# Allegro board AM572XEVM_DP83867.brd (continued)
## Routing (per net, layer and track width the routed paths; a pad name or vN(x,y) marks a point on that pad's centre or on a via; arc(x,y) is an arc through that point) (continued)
DDR1_DQSN0: length 24
  TOP w0.102: U11.AG25 58.6,51.2 58.6,52.28 57.69,53.19 56.03,53.19 54.99,54.23 54.99,58.04 53.34,59.69 50.67,59.69 48.27,57.3 43.42,57.3 43.02,57.7 43.02,57.97 U23.G3
DDR1_DQSN1: length 21.1
  TOP w0.102: U23.B7 47.06,54.81 47.16,54.71 47.16,54.53 47.03,54.4 46.62,54.4 46.52,54.5 46.52,54.64 46.58,54.7 46.58,55.06 46.68,55.16 48.22,55.16 48.37,55.02 48.87,55.02 49.22,54.67 49.22,53.78 49.53,53.47 50.02,53.47 50.33,53.78 50.33,54.91 50.43,55.02 50.64,55.02 50.74,54.91 50.74,53.78 51.05,53.47 51.55,53.47 51.86,53.78 51.86,55.03 51.97,55.15 52.36,55.15 52.46,55.04 52.46,52.31 55.53,49.24 56.55,49.24 U11.AE28
DDR1_DQSN2: length 24.8
  TOP w0.102: U11.AD28 56.53,48.46 54.84,48.46 51.71,51.59 46.89,51.59 46.71,51.41 46.71,49.94 46.86,49.78 48.76,49.78 49.12,49.42 49.12,46.97 48.22,46.06 43.64,46.06 43.33,46.37 43.33,46.69 43.22,46.81 U24.G3
DDR1_DQSN3: length 19.2
  TOP w0.102: U11.Y27 56.98,45.61 52.25,45.61 51.94,45.3 51.94,44.38 52.25,44.07 53.21,44.07 53.47,43.81 53.47,42.42 52.45,41.4 49.65,41.4 49.12,41.93 49.12,43.32 48.09,44.35 47.47,44.35 47.04,43.91 47.04,43.66 U24.B7
DDR1_DQSN_ECC: length 2
  TOP w0.12: U11.V28 v2(56.19,44.01)
  BOTTOM w0.12: R273.2 55.91,44.01 v2(56.19,44.01)
DDR1_ODT0: length 51.1
  TOP w0.12: v2(40.18,60.01) U23.K1 ; v2(40.18,48.81) U24.K1 ; U11.AE20 v2(62.59,49.61)
  INT_L3 w0.094: v2(62.59,49.61) 62.59,49.81 62.16,50.23 62.16,50.56 61.9,50.83 61.63,50.83 61.36,51.09 61.36,51.36 61.1,51.63 60.83,51.63 60.56,51.89 60.56,52.47 59.56,53.47 58.17,53.47 57.15,54.48 57.15,55.5 56.77,55.88 56.6,55.88 56.36,55.64 56.25,55.64 56.16,55.72 56.16,55.84 56.43,56.1 56.43,56.22 56.35,56.3 56.23,56.3 55.97,56.04 55.85,56.04 55.77,56.12 55.77,56.24 56.03,56.5 56.03,56.62 55.95,56.7 55.83,56.7 55.57,56.44 55.45,56.44 55.37,56.52 55.37,56.64 55.63,56.9 55.63,57.02 55.55,57.1 55.43,57.1 55.17,56.84 55.05,56.84 54.97,56.92 54.97,57.04 55.23,57.3 55.23,57.42 55.15,57.5 55.03,57.5 54.77,57.23 54.65,57.23 54.57,57.32 54.57,57.43 54.83,57.7 54.83,57.82 54.75,57.9 54.63,57.9 54.37,57.63 54.25,57.63 54.17,57.72 54.17,57.83 54.44,58.1 54.44,58.21 54.28,58.37 54.16,58.37 53.83,58.04 53.72,58.04 53.63,58.13 53.63,58.24 53.96,58.57 53.96,58.69 51.44,61.21 40.01,61.21 39.75,60.96 39.75,60.44 v2(40.18,60.01) 40.18,59.77 40.58,59.37 40.58,58.22 41.4,57.4 41.4,50.29 40.18,49.07 v2(40.18,48.81)
  BOTTOM w0.12: R360.1 v2(40.18,48.81)
DDR1_RASN: length 50.8
  TOP w0.12: v2(40.98,47.21) U24.J3 ; U11.AF20 v2(63.39,49.61) ; v2(40.98,58.41) U23.J3
  INT_L3 w0.094: v2(63.39,49.61) 62.96,49.18 62.4,49.18 62.16,49.42 62.16,49.76 61.9,50.03 61.63,50.03 61.36,50.29 61.36,50.56 61.1,50.83 60.83,50.83 60.56,51.09 60.56,51.36 60.3,51.63 60.03,51.63 59.76,51.89 59.76,52.16 58.84,53.09 57.66,53.09 56.52,54.23 55.75,54.23 52.99,56.99 52.99,58.38 53.19,58.58 53.19,58.7 53.11,58.78 52.99,58.78 52.79,58.58 52.67,58.58 52.59,58.66 52.59,58.78 52.79,58.98 52.79,59.1 52.71,59.18 52.59,59.18 52.39,58.98 52.27,58.98 52.19,59.06 52.19,59.18 52.39,59.38 52.39,59.49 52.31,59.58 52.19,59.58 51.99,59.38 51.88,59.38 51.79,59.46 51.79,59.58 51.99,59.78 51.99,59.89 51.91,59.98 51.79,59.98 51.59,59.77 51.48,59.77 51.39,59.86 51.39,59.97 51.6,60.17 51.6,60.29 51.51,60.37 51.4,60.37 51.2,60.17 51.08,60.17 51,60.26 51,60.37 51.2,60.57 51.2,60.69 51.11,60.77 51,60.77 50.8,60.57 50.68,60.57 50.42,60.83 41.02,60.83 40.58,60.39 40.58,59.84 40.82,59.61 41.15,59.61 41.38,59.37 41.38,58.81 v2(40.98,58.41) 41.78,57.61 41.78,50.16 40.82,49.21 40.82,49.21 40.58,48.97 40.58,47.61 v2(40.98,47.21)
  BOTTOM w0.12: R372.1 v2(40.98,47.21)
DDR1_RST: length 50
  TOP w0.12: v2(35.38,59.21) U23.T2 ; U11.AG21 v2(61.79,51.21) ; v2(35.38,48.01) U24.T2
  SIG_L5 w0.094: v2(35.38,59.21) 34.98,58.81 34.98,57.91 35.56,57.33 35.56,55.44 34.98,54.86 34.98,52.45 35.38,52.05 TP20.1 35.38,49.68 34.98,49.28 34.98,48.41 v2(35.38,48.01)
  SIG_L8 w0.094: v2(35.38,59.21) 34.92,58.75 34.92,58.06 35.01,57.98 35.35,57.98 35.43,57.89 35.43,57.78 35.35,57.7 35.01,57.7 34.92,57.61 34.92,57.5 35.01,57.41 35.35,57.41 35.43,57.33 35.43,57.21 35.35,57.13 35.01,57.13 34.92,57.05 34.92,56.64 35.31,56.26 44.32,56.26 44.58,56.01 44.58,51.82 44.81,51.58 60.83,51.58 60.83,51.58 61.45,51.58 61.79,51.24 v2(61.79,51.21)
DDR1_WEN: length 50.8
  TOP w0.12: v2(39.38,47.21) U24.L3 ; U11.AH21 v2(61.79,52.01) ; v2(39.38,58.41) U23.L3
  INT_L3 w0.094: v2(39.38,58.41) 39.38,57.9 40.13,57.15 40.13,55.88 38.98,54.73 38.98,47.61 v2(39.38,47.21)
  SIG_L8 w0.094: v2(39.38,58.41) 40.13,57.66 42.07,57.66 42.15,57.58 42.15,57.36 42.23,57.28 42.35,57.28 42.43,57.36 42.43,57.58 42.51,57.66 42.63,57.66 42.71,57.58 42.71,57.36 42.79,57.28 42.91,57.28 42.99,57.36 42.99,57.58 43.08,57.66 43.19,57.66 43.28,57.58 43.28,57.36 43.36,57.28 43.48,57.28 43.56,57.36 43.56,57.58 43.64,57.66 43.76,57.66 43.84,57.58 43.84,57.36 43.92,57.28 44.04,57.28 44.12,57.36 44.12,57.58 44.2,57.66 44.32,57.66 44.4,57.58 44.4,57.36 44.49,57.28 44.6,57.28 44.69,57.36 44.69,57.58 44.77,57.66 44.89,57.66 44.97,57.58 44.97,57.36 45.05,57.28 45.17,57.28 45.25,57.36 45.25,57.58 45.33,57.66 45.45,57.66 45.53,57.58 45.53,57.36 45.61,57.28 45.73,57.28 45.81,57.36 45.81,57.58 45.9,57.66 46.01,57.66 46.1,57.58 46.1,57.36 46.18,57.28 46.3,57.28 46.38,57.36 46.38,57.58 46.46,57.66 46.58,57.66 46.66,57.58 46.66,57.36 46.74,57.28 46.86,57.28 46.94,57.36 46.94,57.58 47.02,57.66 47.14,57.66 47.22,57.58 47.22,57.36 47.31,57.28 47.42,57.28 47.51,57.36 47.51,57.58 47.59,57.66 48.01,57.66 48.16,57.5 48.16,57.38 48.03,57.25 48.03,57.13 48.11,57.05 48.22,57.05 48.36,57.19 48.48,57.19 48.56,57.1 48.56,56.99 48.42,56.85 48.42,56.73 48.51,56.65 48.62,56.65 48.76,56.79 48.88,56.79 48.96,56.7 48.96,56.59 48.82,56.45 48.82,56.33 48.91,56.25 49.02,56.25 49.16,56.39 49.28,56.39 49.36,56.31 49.36,56.19 49.22,56.05 49.22,55.93 49.3,55.85 49.42,55.85 49.56,55.99 49.67,55.99 49.76,55.91 49.76,55.79 49.62,55.65 49.62,55.54 49.7,55.45 49.82,55.45 49.96,55.59 50.07,55.59 50.16,55.51 50.16,55.39 50.02,55.25 50.02,55.14 50.1,55.05 50.22,55.05 50.36,55.19 50.47,55.19 50.55,55.11 50.55,54.99 50.42,54.86 50.42,54.74 50.5,54.66 50.62,54.66 50.75,54.79 50.87,54.79 50.95,54.71 50.95,54.59 50.82,54.46 50.82,54.34 50.9,54.26 51.02,54.26 51.15,54.39 51.27,54.39 51.35,54.31 51.35,54.2 51.21,54.06 51.21,53.94 51.3,53.86 51.41,53.86 51.55,54 51.67,54 51.75,53.91 51.75,53.8 51.61,53.66 51.61,53.54 51.7,53.46 51.81,53.46 51.95,53.6 52.07,53.6 52.15,53.51 52.15,53.4 52.01,53.26 52.01,53.14 52.2,52.96 60.83,52.96 v2(61.79,52.01)
  BOTTOM w0.12: R374.1 v2(39.38,47.21)
DDR2_A0: length 48.3
  TOP w0.12: v2(37.78,24.8) U25.N3 ; U11.R25 v2(58.59,41.61) ; v2(37.78,36) U26.N3
  INT_L3 w0.094: v2(37.78,24.8) 37.38,25.2 37.38,32.25 38.61,33.48 38.61,34.68 37.78,35.51 v2(37.78,36)
  SIG_L8 w0.094: v2(58.59,41.61) 58.13,41.15 54.23,41.15 53.34,40.26 53.21,40.26 52.83,40.64 52.7,40.64 52.55,40.48 52.55,40.37 52.94,39.98 52.94,39.86 52.86,39.78 52.74,39.78 52.35,40.17 52.23,40.17 52.15,40.09 52.15,39.97 52.54,39.58 52.54,39.46 52.46,39.38 52.34,39.38 51.95,39.77 51.83,39.77 51.75,39.69 51.75,39.57 52.14,39.18 52.14,39.06 52.06,38.98 51.94,38.98 51.55,39.37 51.44,39.37 51.35,39.29 51.35,39.17 51.74,38.78 51.74,38.66 51.66,38.58 51.54,38.58 51.15,38.97 51.04,38.97 50.95,38.89 50.95,38.77 51.35,38.38 51.35,38.26 51.26,38.18 51.15,38.18 50.75,38.57 50.64,38.57 50.56,38.49 50.56,38.37 50.82,38.11 50.82,37.99 50.74,37.91 50.62,37.91 50.36,38.17 50.24,38.17 50.08,38.02 50.08,37.9 50.28,37.7 50.28,37.58 50.2,37.5 50.08,37.5 49.88,37.7 49.77,37.7 49.68,37.62 49.68,37.5 49.88,37.3 49.88,37.18 49.8,37.1 49.69,37.1 49.58,37.2 42.28,37.2 42.16,37.08 42.16,35.56 41.78,35.18 38.1,35.18 37.78,35.5 v2(37.78,36)
  BOTTOM w0.12: R355.1 v2(37.78,24.8)
DDR2_A1: length 48.8
  TOP w0.12: v2(36.98,32) U26.P7 ; v2(36.98,20.8) U25.P7 ; U11.R26 v2(57.79,41.61)
  SIG_L8 w0.094: v2(36.98,32) 38.25,33.27 50.93,33.27 54.74,37.08 55.27,37.08 55.35,37.17 55.35,37.51 55.44,37.59 55.55,37.59 55.64,37.51 55.64,37.17 55.72,37.08 55.83,37.08 55.92,37.17 55.92,37.51 56,37.59 56.12,37.59 56.2,37.51 56.2,37.17 56.28,37.08 56.4,37.08 56.48,37.17 56.48,37.51 56.56,37.59 56.68,37.59 56.76,37.51 56.76,37.17 56.85,37.08 56.96,37.08 57.04,37.17 57.04,37.51 57.13,37.59 57.24,37.59 57.33,37.51 57.33,37.17 57.41,37.08 57.8,37.08 58.16,37.45 58.16,37.72 58.47,38.03 58.74,38.03 58.96,38.25 58.96,40.17 59.81,41.01 59.81,41.79 59.57,42.03 58.21,42.03 v2(57.79,41.61)
  SIG_L10 w0.094: v2(36.98,20.8) 36.58,21.2 36.58,21.54 37.03,21.99 37.03,23.95 36.58,24.4 36.58,26.8 37.03,27.25 37.03,28.02 36.58,28.47 36.58,31.6 v2(36.98,32)
  BOTTOM w0.12: R356.1 v2(36.98,20.8)
DDR2_A2: length 48.8
  TOP w0.12: U11.R28 v2(56.19,41.61) ; v2(36.98,36) U26.P3 ; v2(36.98,24.8) U25.P3
  INT_L3 w0.094: v2(36.98,24.8) 36.58,25.2 36.58,32.21 37.85,33.48 37.85,34.65 36.98,35.51 v2(36.98,36)
  SIG_L8 w0.094: v2(36.98,36) 37.38,36.4 37.95,36.4 38.18,36.17 38.18,35.73 38.35,35.56 41.28,35.56 41.78,36.07 41.78,37.72 42.16,38.1 49.02,38.1 49.6,38.68 49.72,38.68 49.85,38.54 49.97,38.54 50.05,38.62 50.05,38.74 49.91,38.88 49.91,38.99 50,39.08 50.11,39.08 50.25,38.94 50.37,38.94 50.45,39.02 50.45,39.14 50.31,39.27 50.31,39.39 50.4,39.47 50.51,39.47 50.65,39.34 50.77,39.34 50.85,39.42 50.85,39.54 50.71,39.67 50.71,39.79 50.79,39.87 50.91,39.87 51.05,39.74 51.17,39.74 51.25,39.82 51.25,39.94 51.11,40.07 51.11,40.19 51.19,40.27 51.31,40.27 51.45,40.13 51.56,40.13 51.65,40.22 51.65,40.33 51.51,40.47 51.51,40.59 51.59,40.67 51.71,40.67 51.85,40.53 51.96,40.53 52.05,40.62 52.05,40.73 51.91,40.87 51.91,40.99 51.99,41.07 52.11,41.07 52.25,40.93 52.36,40.93 52.44,41.01 52.44,41.13 52.31,41.27 52.31,41.39 52.53,41.61 53.11,41.61 53.19,41.69 53.19,42.34 53.27,42.42 53.39,42.42 53.47,42.34 53.47,41.69 53.55,41.61 53.67,41.61 53.75,41.69 53.75,42.34 53.84,42.42 53.95,42.42 54.03,42.34 54.03,41.69 54.12,41.61 54.23,41.61 54.32,41.69 54.32,42.34 54.4,42.42 54.52,42.42 54.6,42.34 54.6,41.69 54.68,41.61 54.8,41.61 54.88,41.69 54.88,42.34 54.96,42.42 55.08,42.42 55.16,42.34 55.16,41.69 55.25,41.61 55.36,41.61 55.44,41.69 55.44,42.34 55.53,42.42 55.64,42.42 55.73,42.34 55.73,41.69 55.81,41.61 v2(56.19,41.61)
  BOTTOM w0.12: R346.1 v2(36.98,24.8)
DDR2_A3: length 49.9
  TOP w0.12: U11.R27 v2(56.99,41.61) ; v2(37.78,36.8) U26.N2 ; v2(37.78,25.6) U25.N2
  SIG_L5 w0.094: v2(56.99,41.61) 56.53,41.15 55.48,41.15 55.4,41.23 55.4,41.57 55.32,41.66 55.2,41.66 55.12,41.57 55.12,41.23 55.04,41.15 54.92,41.15 54.84,41.23 54.84,41.57 54.76,41.66 54.64,41.66 54.56,41.57 54.56,41.23 54.47,41.15 54.36,41.15 54.27,41.23 54.27,41.57 54.19,41.66 54.07,41.66 53.99,41.57 53.99,40.84 53.9,40.75 53.14,40.75 53.06,40.83 53.06,41.57 52.98,41.66 52.86,41.66 52.78,41.57 52.78,40.83 52.69,40.75 52.58,40.75 52.49,40.83 52.49,41.57 52.41,41.66 52.29,41.66 52.21,41.57 52.21,40.83 52.13,40.75 52.01,40.75 51.93,40.83 51.93,41.57 51.85,41.66 51.73,41.66 51.65,41.57 51.65,40.83 51.57,40.75 51.45,40.75 51.37,40.83 51.37,41.57 51.28,41.66 51.17,41.66 51.08,41.57 51.08,40.83 51,40.75 50.88,40.75 50.8,40.83 50.8,41.57 50.72,41.66 50.6,41.66 50.52,41.57 50.52,40.83 50.34,40.65 50.22,40.65 50,40.87 49.89,40.87 49.8,40.79 49.8,40.67 50.03,40.45 50.03,40.33 49.94,40.25 49.83,40.25 49.6,40.47 49.49,40.47 49.41,40.39 49.41,40.27 49.63,40.05 49.63,39.93 48.94,39.24 39.66,39.24 38.18,37.77 38.18,37.17 37.82,36.8 v2(37.78,36.8) 37.78,36.68 37.38,36.28 37.38,33.1 38.23,32.26 38.23,29.89 38.1,29.76 38.1,29.61 38.23,29.48 38.23,29.32 38.1,29.2 38.1,29.04 38.23,28.92 38.23,28.76 38.1,28.63 38.1,28.48 38.23,28.35 38.23,28.2 38.1,28.07 38.1,27.91 38.23,27.79 38.23,27.63 38.1,27.51 38.1,27.35 38.23,27.22 38.23,27.07 38.1,26.94 38.1,26.79 38.23,26.66 38.23,26.05 v2(37.78,25.6)
  BOTTOM w0.12: v2(37.78,25.6) 38.18,26 38.18,26.6 R344.1
DDR2_A4: length 50
  TOP w0.12: v2(36.98,31.2) U26.P8 ; U11.P23 v2(60.19,40.01) ; v2(36.98,20) U25.P8
  SIG_L8 w0.094: v2(60.19,40.01) 60.61,39.58 60.61,39.05 60.83,38.83 61.12,38.83 61.36,38.59 61.36,38.25 61.14,38.03 61.1,37.98 60.83,37.98 60.61,37.76 60.61,37.5 60.56,37.45 60.56,37.45 60.34,37.23 60.3,37.18 60.03,37.18 59.81,36.96 59.81,36.7 59.76,36.65 59.76,36.65 59.54,36.43 59.5,36.38 59.23,36.38 59.01,36.16 59.01,35.9 58.96,35.85 58.96,35.85 58.74,35.63 58.7,35.58 58.43,35.58 58.21,35.36 58.21,35.1 58.16,35.05 58.16,35.05 57.94,34.83 57.91,34.8 57.53,34.8 55.65,32.91 55.65,31.39 54.74,30.48 50.55,30.48 49.02,28.96 40.13,28.96 38.98,30.11 38.98,31.38 38.75,31.6 U26.P8 v2(36.98,31.2) 36.58,30.8 36.58,29.92 37.08,29.42 37.08,27.37 36.58,26.87 36.58,24.33 37.08,23.83 37.08,21.79 36.58,21.29 36.58,20.4 v2(36.98,20)
  BOTTOM w0.12: R347.1 37.38,19 37.38,19.6 v2(36.98,20)
DDR2_A5: length 49.5
  TOP w0.12: U11.P22 v2(60.99,40.01) ; v2(36.98,36.8) U26.P2 ; v2(36.98,25.6) U25.P2
  SIG_L5 w0.094: v2(60.99,40.01) 60.61,40.38 60.61,41.72 60.3,42.03 55.75,42.03 55.66,42.11 55.66,42.34 55.58,42.42 55.46,42.42 55.38,42.34 55.38,42.11 55.3,42.03 55.18,42.03 55.1,42.11 55.1,42.34 55.02,42.42 54.9,42.42 54.82,42.34 54.82,42.11 54.74,42.03 54.62,42.03 54.54,42.11 54.54,42.34 54.45,42.42 54.34,42.42 54.25,42.34 54.25,42.11 54.17,42.03 54.05,42.03 53.97,42.11 53.97,42.34 53.89,42.42 53.77,42.42 53.69,42.34 53.69,42.11 53.61,42.03 53.49,42.03 53.41,42.11 53.41,42.34 53.33,42.42 53.21,42.42 53.13,42.34 53.13,42.11 53.04,42.03 52.93,42.03 52.84,42.11 52.84,42.34 52.76,42.42 52.64,42.42 52.56,42.34 52.56,42.11 52.48,42.03 52.36,42.03 52.28,42.11 52.28,42.34 52.2,42.42 52.08,42.42 52,42.34 52,42.11 51.92,42.03 51.8,42.03 51.72,42.11 51.72,42.34 51.63,42.42 51.52,42.42 51.43,42.34 51.43,42.11 51.35,42.03 51.24,42.03 51.15,42.11 51.15,42.34 51.07,42.42 50.95,42.42 50.87,42.34 50.87,42.11 50.79,42.03 50.16,42.03 48.26,40.13 39.37,40.13 37.38,38.14 37.38,37.26 36.98,36.86 v2(36.98,36.8) 36.98,36.68 36.58,36.28 36.58,33.01 37.34,32.26 37.34,29.87 37.21,29.75 37.21,29.59 37.34,29.46 37.34,29.31 37.21,29.18 37.21,29.03 37.34,28.9 37.34,28.74 37.21,28.62 37.21,28.46 37.34,28.34 37.34,28.18 37.21,28.05 37.21,27.9 37.34,27.77 37.34,27.62 37.21,27.49 37.21,27.34 37.34,27.21 37.34,27.05 37.21,26.93 37.21,26.77 37.34,26.64 37.34,25.96 v2(36.98,25.6)
  BOTTOM w0.12: v2(36.98,25.6) 37.38,26 37.38,26.6 R345.1
DDR2_A6: length 49.5
  TOP w0.12: v2(36.18,20) U25.R8 ; v2(36.18,31.2) U26.R8 ; U11.P25 v2(58.59,40.01)
  SIG_L8 w0.094: v2(58.59,40.01) 58.21,39.63 58.21,38.27 57.92,37.98 55,37.98 54.83,37.81 54.71,37.81 54.55,37.98 54.43,37.98 54.35,37.89 54.35,37.78 54.51,37.61 54.51,37.5 54.43,37.41 54.32,37.41 54.15,37.58 54.04,37.58 53.95,37.49 53.95,37.38 54.12,37.21 54.12,37.1 54.03,37.02 53.92,37.02 53.75,37.18 53.64,37.18 53.55,37.1 53.55,36.98 53.72,36.82 53.72,36.7 53.63,36.62 53.52,36.62 53.35,36.78 53.24,36.78 53.16,36.7 53.16,36.58 53.32,36.42 53.32,36.3 53.24,36.22 53.12,36.22 52.96,36.38 52.84,36.38 52.76,36.3 52.76,36.18 52.92,36.02 52.92,35.9 52.84,35.82 52.72,35.82 52.56,35.98 52.44,35.98 52.36,35.9 52.36,35.78 52.52,35.62 52.52,35.5 52.44,35.42 52.32,35.42 52.16,35.58 52.04,35.58 51.96,35.5 51.96,35.38 52.12,35.22 52.12,35.1 52.04,35.02 51.92,35.02 51.76,35.19 51.64,35.19 51.56,35.1 51.56,34.99 51.72,34.82 51.72,34.71 51.64,34.62 51.52,34.62 51.36,34.79 51.24,34.79 51.16,34.7 51.16,34.59 51.33,34.42 51.33,34.31 51.24,34.22 51.13,34.22 50.96,34.39 50.85,34.39 50.76,34.3 50.76,34.19 50.93,34.03 50.93,33.91 50.67,33.66 37.08,33.66 36.58,33.15 U26.R8 v2(36.18,31.2) 35.78,30.8 35.78,29.92 36.32,29.38 36.32,27.41 35.78,26.87 35.78,24.33 36.2,23.92 36.2,21.7 35.78,21.29 35.78,20.4 v2(36.18,20)
  BOTTOM w0.12: v2(36.18,20) 36.58,19.6 36.58,19 R338.1
DDR2_A7: length 50.1
  TOP w0.12: v2(36.18,36.8) U26.R2 ; U11.N20 v2(62.59,39.21) ; v2(36.18,25.6) U25.R2
  SIG_L5 w0.094: v2(62.59,39.21) 62.21,39.58 62.21,41.72 61.94,41.98 60.83,41.98 60.58,42.24 60.58,42.55 60.56,42.56 60.56,42.56 60.34,42.78 60.33,42.8 54.8,42.8 54.72,42.88 54.72,42.97 54.63,43.05 54.52,43.05 54.43,42.97 54.43,42.88 54.35,42.8 54.24,42.8 54.15,42.88 54.15,42.97 54.07,43.05 53.95,43.05 53.87,42.97 53.87,42.88 53.79,42.8 53.67,42.8 53.59,42.88 53.59,42.97 53.51,43.05 53.39,43.05 53.31,42.97 53.31,42.88 53.22,42.8 53.11,42.8 53.02,42.88 53.02,42.97 52.94,43.05 52.83,43.05 52.74,42.97 52.74,42.88 52.66,42.8 52.54,42.8 52.46,42.88 52.46,42.97 52.38,43.05 52.26,43.05 52.18,42.97 52.18,42.88 52.1,42.8 51.98,42.8 51.9,42.88 51.9,42.97 51.81,43.05 51.7,43.05 51.62,42.97 51.62,42.88 51.53,42.8 50.42,42.8 48.13,40.51 39.12,40.51 36.58,37.98 36.58,37.22 36.18,36.82 v2(36.18,36.8) 36.18,36.56 36.02,36.4 36.02,36.4 35.78,36.17 35.78,33.05 36.58,32.26 36.58,29.9 36.45,29.78 36.45,29.62 36.58,29.49 36.58,29.34 36.45,29.21 36.45,29.06 36.58,28.93 36.58,28.78 36.45,28.65 36.45,28.49 36.58,28.37 36.58,28.21 36.45,28.09 36.45,27.93 36.58,27.8 36.58,27.65 36.45,27.52 36.45,27.37 36.58,27.24 36.58,27.08 36.45,26.96 36.45,26.8 36.58,26.68 36.58,26 v2(36.18,25.6)
  BOTTOM w0.12: R358.1 36.58,26.6 36.58,26 v2(36.18,25.6)
DDR2_A8: length 49.8
  TOP w0.12: U11.P27 v2(56.99,40.01) ; v2(35.38,20) U25.T8 ; v2(35.38,31.2) U26.T8
  SIG_L8 w0.094: v2(56.99,40.01) 57.4,39.59 57.4,39.09 57.14,38.83 55.88,38.83 55.46,39.24 54.74,39.24 50.67,35.18 50.3,35.18 50.22,35.1 50.22,34.88 50.14,34.8 50.02,34.8 49.94,34.88 49.94,35.1 49.85,35.18 49.74,35.18 49.65,35.1 49.65,34.88 49.57,34.8 49.46,34.8 49.37,34.88 49.37,35.1 49.29,35.18 49.17,35.18 49.09,35.1 49.09,34.88 49.01,34.8 48.89,34.8 48.81,34.88 48.81,35.1 48.73,35.18 48.61,35.18 48.53,35.1 48.53,34.88 48.44,34.8 48.33,34.8 48.24,34.88 48.24,35.1 48.16,35.18 48.05,35.18 47.96,35.1 47.96,34.88 47.88,34.8 47.76,34.8 47.68,34.88 47.68,35.1 47.6,35.18 47.48,35.18 47.4,35.1 47.4,34.88 47.32,34.8 47.2,34.8 47.12,34.88 47.12,35.1 47.03,35.18 46.92,35.18 46.84,35.1 46.84,34.88 46.75,34.8 46.64,34.8 46.55,34.88 46.55,35.1 46.47,35.18 46.35,35.18 46.27,35.1 46.27,34.88 46.19,34.8 46.07,34.8 45.99,34.88 45.99,35.1 45.91,35.18 45.79,35.18 45.71,35.1 45.71,34.88 45.62,34.8 45.51,34.8 45.43,34.88 45.43,35.1 45.34,35.18 45.23,35.18 45.14,35.1 45.14,34.88 45.06,34.8 44.94,34.8 44.86,34.88 44.86,35.1 44.78,35.18 44.66,35.18 44.58,35.1 44.58,34.88 44.5,34.8 44.38,34.8 44.3,34.88 44.3,35.1 44.21,35.18 43.43,35.18 42.61,34.35 36.64,34.35 35.78,33.5 U26.T8 v2(35.38,31.2) 34.98,30.8 34.98,30.05 34.54,29.61 34.54,27.31 34.98,26.87 34.98,24.46 35.43,24.01 35.43,21.74 34.98,21.29 34.98,20.4 v2(35.38,20)
  BOTTOM w0.12: v2(35.38,20) 35.78,19.6 35.78,19 R359.1
DDR2_A9: length 48.4
  TOP w0.12: U11.N27 v2(56.99,39.21) ; v2(36.18,24.8) U25.R3 ; v2(36.18,36) U26.R3
  INT_L3 w0.094: v2(36.18,24.8) 35.78,25.2 35.78,32.18 37.08,33.48 37.08,34.61 36.18,35.51 v2(36.18,36)
  SIG_L8 w0.094: v2(56.99,39.21) 56.61,39.58 53.68,39.58 53.49,39.39 53.49,39.27 53.81,38.95 53.81,38.83 53.73,38.75 53.61,38.75 53.29,39.07 53.17,39.07 53.09,38.99 53.09,38.87 53.42,38.55 53.42,38.43 53.33,38.35 53.22,38.35 52.89,38.67 52.77,38.67 52.69,38.59 52.69,38.48 53.02,38.15 53.02,38.03 52.93,37.95 52.82,37.95 52.49,38.28 52.37,38.28 52.29,38.19 52.29,38.08 52.62,37.75 52.62,37.63 52.54,37.55 52.42,37.55 52.09,37.88 51.97,37.88 51.89,37.79 51.89,37.68 52.22,37.35 52.22,37.23 52.14,37.15 52.02,37.15 51.69,37.48 51.58,37.48 51.49,37.4 51.49,37.28 51.82,36.95 51.82,36.83 51.74,36.75 51.62,36.75 51.42,36.95 51.3,36.95 51.22,36.87 51.22,36.75 51.42,36.55 51.42,36.44 51.34,36.35 51.22,36.35 50.89,36.68 50.78,36.68 50.7,36.6 50.7,36.48 51.02,36.15 51.02,36.04 50.94,35.95 50.82,35.95 50.5,36.28 50.38,36.28 50.3,36.2 50.3,36.08 50.62,35.76 50.62,35.64 50.54,35.56 50.43,35.56 50.1,35.88 49.98,35.88 49.66,35.56 43.31,35.56 42.42,34.67 36.2,34.67 35.81,35.05 35.81,35.64 v2(36.18,36)
  BOTTOM w0.12: R336.1 v2(36.18,24.8)
DDR2_A10: length 48
  TOP w0.12: v2(39.38,20.8) U25.L7 ; v2(39.38,32) U26.L7 ; U11.N23 v2(60.19,39.21)
  SIG_L8 w0.094: v2(60.19,39.21) 60.19,39 60.58,38.61 60.58,38.26 60.34,38.03 60.03,38.03 59.76,37.76 59.76,37.45 59.54,37.23 59.23,37.23 58.16,36.16 58.16,35.85 57.94,35.63 57.47,35.63 56.32,34.48 56.2,34.48 55.94,34.74 55.82,34.74 55.74,34.66 55.74,34.54 56,34.28 56,34.16 55.92,34.08 55.8,34.08 55.54,34.34 55.42,34.34 55.34,34.26 55.34,34.14 55.6,33.88 55.6,33.76 55.52,33.68 55.41,33.68 55.14,33.94 55.02,33.94 54.94,33.86 54.94,33.74 55.21,33.48 55.21,33.36 55.12,33.28 55.01,33.28 54.74,33.54 54.63,33.54 54.54,33.46 54.54,33.34 54.81,33.08 54.81,32.96 54.72,32.88 54.61,32.88 54.34,33.14 54.23,33.14 54.14,33.06 54.14,32.95 54.41,32.68 54.41,32.56 53.98,32.13 53.98,31.24 53.72,30.99 50.29,30.99 48.64,29.34 40.26,29.34 39.78,29.81 39.78,31.6 v2(39.38,32)
  SIG_L10 w0.094: v2(39.38,20.8) 38.98,21.2 38.98,21.54 39.43,21.99 39.43,23.95 38.98,24.4 38.98,26.8 39.43,27.25 39.43,29.67 38.98,30.12 38.98,31.6 v2(39.38,32)
  BOTTOM w0.12: R340.1 v2(39.38,20.8)
DDR2_A11: length 48.3
  TOP w0.12: U11.P26 v2(57.79,40.01) ; v2(36.18,32) U26.R7 ; v2(36.18,20.8) U25.R7
  SIG_L8 w0.094: v2(57.79,40.01) 57.79,38.94 57.33,38.48 55.75,38.48 55.37,38.86 54.86,38.86 50.22,34.22 50.22,34.12 50.14,34.04 50.02,34.04 49.94,34.12 49.94,34.33 49.86,34.42 49.74,34.42 49.66,34.33 49.66,34.12 49.58,34.04 49.46,34.04 49.38,34.12 49.38,34.33 49.29,34.42 49.18,34.42 49.09,34.33 49.09,34.12 49.01,34.04 48.9,34.04 48.81,34.12 48.81,34.33 48.73,34.42 48.61,34.42 48.53,34.33 48.53,34.12 48.45,34.04 48.33,34.04 48.25,34.12 48.25,34.33 48.17,34.42 48.05,34.42 47.97,34.33 47.97,34.12 47.88,34.04 47.77,34.04 47.68,34.12 47.68,34.33 47.6,34.42 47.49,34.42 47.4,34.33 47.4,34.12 47.32,34.04 47.2,34.04 47.12,34.12 47.12,34.33 47.04,34.42 46.92,34.42 46.84,34.33 46.84,34.12 46.76,34.04 46.64,34.04 46.56,34.12 46.56,34.33 46.47,34.42 46.36,34.42 46.28,34.33 46.28,34.12 46.19,34.04 46.08,34.04 45.99,34.12 45.99,34.33 45.91,34.42 45.79,34.42 45.71,34.33 45.71,34.12 45.63,34.04 45.51,34.04 45.43,34.12 45.43,34.33 45.35,34.42 45.23,34.42 45.15,34.33 45.15,34.12 45.06,34.04 44.95,34.04 44.87,34.12 44.87,34.33 44.78,34.42 44.67,34.42 44.58,34.33 44.58,34.12 44.5,34.04 44.38,34.04 44.3,34.12 44.3,34.33 44.22,34.42 44.1,34.42 44.02,34.33 44.02,34.12 43.94,34.04 43.82,34.04 43.74,34.12 43.74,34.62 43.64,34.72 43.48,34.72 42.8,34.04 36.96,34.04 36.2,33.27 36.2,32.02 v2(36.18,32)
  SIG_L10 w0.094: v2(36.18,32) 35.78,31.6 35.78,28.47 36.23,28.02 36.23,27.25 35.78,26.8 35.78,24.4 36.23,23.95 36.23,21.99 35.78,21.54 35.78,21.2 v2(36.18,20.8)
  BOTTOM w0.12: R337.1 v2(36.18,20.8)
DDR2_A12: length 48.5
  TOP w0.12: v2(37.78,32) U26.N7 ; v2(37.78,20.8) U25.N7 ; U11.N28 v2(56.19,39.21)
  SIG_L8 w0.094: v1(55.25,36.01) 51.75,32.51 51.57,32.51 51.49,32.59 51.49,32.81 51.41,32.89 51.29,32.89 51.21,32.81 51.21,32.59 51.13,32.51 51.01,32.51 50.93,32.59 50.93,32.81 50.85,32.89 50.73,32.89 50.65,32.81 50.65,32.59 50.56,32.51 50.45,32.51 50.36,32.59 50.36,32.81 50.28,32.89 50.16,32.89 50.08,32.81 50.08,32.59 50,32.51 49.88,32.51 49.8,32.59 49.8,32.81 49.72,32.89 49.6,32.89 49.52,32.81 49.52,32.59 49.44,32.51 49.32,32.51 49.24,32.59 49.24,32.81 49.15,32.89 49.04,32.89 48.95,32.81 48.95,32.59 48.87,32.51 48.75,32.51 48.67,32.59 48.67,32.81 48.59,32.89 48.47,32.89 48.39,32.81 48.39,32.59 48.31,32.51 48.19,32.51 48.11,32.59 48.11,32.81 48.03,32.89 47.91,32.89 47.83,32.81 47.83,32.59 47.74,32.51 47.63,32.51 47.54,32.59 47.54,32.81 47.46,32.89 47.35,32.89 47.26,32.81 47.26,32.59 47.18,32.51 47.06,32.51 46.98,32.59 46.98,32.81 46.9,32.89 46.78,32.89 46.7,32.81 46.7,32.59 46.62,32.51 46.5,32.51 46.42,32.59 46.42,32.81 46.33,32.89 46.22,32.89 46.13,32.81 46.13,32.59 46.05,32.51 45.94,32.51 45.85,32.59 45.85,32.81 45.77,32.89 45.65,32.89 45.57,32.81 45.57,32.59 45.49,32.51 45.37,32.51 45.29,32.59 45.29,32.81 45.21,32.89 45.09,32.89 45.01,32.81 45.01,32.59 44.92,32.51 44.81,32.51 44.73,32.59 44.73,32.81 44.64,32.89 44.53,32.89 44.44,32.81 44.44,32.59 44.36,32.51 44.24,32.51 44.16,32.59 44.16,32.81 44.08,32.89 43.96,32.89 43.88,32.81 43.88,32.59 43.8,32.51 43.68,32.51 43.6,32.59 43.6,32.81 43.51,32.89 43.4,32.89 43.32,32.81 43.32,32.59 43.23,32.51 43.12,32.51 43.03,32.59 43.03,32.81 42.95,32.89 42.83,32.89 42.75,32.81 42.75,32.59 42.67,32.51 42.55,32.51 42.47,32.59 42.47,32.81 42.39,32.89 42.27,32.89 42.19,32.81 42.19,32.59 42.1,32.51 41.99,32.51 41.91,32.59 41.91,32.81 41.82,32.89 41.71,32.89 41.62,32.81 41.62,32.59 41.54,32.51 41.42,32.51 41.34,32.59 41.34,32.81 41.26,32.89 41.14,32.89 41.06,32.81 41.06,32.59 40.98,32.51 40.86,32.51 40.78,32.59 40.78,32.81 40.7,32.89 38.67,32.89 v2(37.78,32)
  SIG_L10 w0.094: v2(37.78,32) 37.38,31.6 37.38,28.47 37.83,28.02 37.83,27.25 37.38,26.8 37.38,24.4 37.83,23.95 37.83,21.99 37.38,21.54 37.38,21.2 v2(37.78,20.8) ; v2(56.19,39.21) 56.19,36.95 v1(55.25,36.01)
  BOTTOM w0.12: R354.1 v2(37.78,20.8)
DDR2_A13: length 48.7
  TOP w0.12: v2(35.38,36) U26.T3 ; U11.T22 v2(60.99,42.41) ; v2(35.38,24.8) U25.T3
  INT_L3 w0.094: v2(35.38,24.8) 34.98,25.2 34.98,32.17 36.32,33.51 36.32,34.62 35.38,35.56 v2(35.38,36)
  SIG_L5 w0.094: v2(35.38,36) 35.38,36.24 35.78,36.64 35.78,37.94 38.73,40.89 48.01,40.89 50.69,43.58 51.41,43.58 51.49,43.66 51.49,43.86 51.58,43.94 51.69,43.94 51.78,43.86 51.78,43.66 51.86,43.58 51.98,43.58 52.06,43.66 52.06,43.86 52.14,43.94 52.26,43.94 52.34,43.86 52.34,43.66 52.42,43.58 52.54,43.58 52.62,43.66 52.62,43.86 52.71,43.94 52.82,43.94 52.9,43.86 52.9,43.66 52.99,43.58 53.1,43.58 53.19,43.66 53.19,43.86 53.27,43.94 53.39,43.94 53.47,43.86 53.47,43.66 53.55,43.58 53.67,43.58 53.75,43.66 53.75,43.86 53.83,43.94 53.95,43.94 54.03,43.86 54.03,43.66 54.11,43.58 54.23,43.58 54.31,43.66 54.31,43.86 54.4,43.94 54.51,43.94 54.6,43.86 54.6,43.66 54.68,43.58 54.8,43.58 54.88,43.66 54.88,43.86 54.96,43.94 55.08,43.94 55.16,43.86 55.16,43.66 55.24,43.58 60.34,43.58 60.61,43.32 60.61,43.05 60.99,42.67 v2(60.99,42.41)
  BOTTOM w0.12: R357.1 v2(35.38,24.8)
DDR2_A14: length 48.5
  TOP w0.12: v2(35.38,32) U26.T7 ; v2(35.38,20.8) U25.T7 ; U11.R22 v2(60.99,41.61)
  SIG_L10 w0.094: v2(60.99,41.61) 60.56,42.03 60.56,42.56 60.34,42.78 60.03,42.78 59.76,43.05 59.76,43.36 59.54,43.58 59.23,43.58 57.63,45.18 55.98,45.18 55.75,44.96 55.75,44.77 51.75,40.77 45.09,40.77 41.78,37.47 41.78,36.2 40.64,35.05 38.43,35.05 v2(35.38,32) 34.98,31.6 34.98,28.47 35.43,28.02 35.43,27.25 34.98,26.8 34.98,24.4 35.43,23.95 35.43,21.99 34.98,21.54 34.98,21.2 v2(35.38,20.8)
  BOTTOM w0.12: R339.1 v2(35.38,20.8)
DDR2_A15: length 48.2
  TOP w0.12: v2(38.58,20.8) U25.M7 ; U11.U22 v2(60.99,43.21) ; v2(38.58,32) U26.M7
  SIG_L8 w0.094: v2(38.58,32) 39.09,32.51 40.39,32.51 40.58,32.32 40.58,30.03 40.89,29.72 48.26,29.72 50.04,31.5 51.44,31.5 55.12,35.18 56.39,35.18 56.56,35.35 56.56,36.24 56.75,36.43 57.64,36.43 58.44,37.23 58.74,37.23 58.96,37.45 58.96,37.75 59.24,38.03 59.54,38.03 59.81,38.29 59.81,40.25 60.58,41.02 60.58,42.8 v2(60.99,43.21)
  SIG_L10 w0.094: v2(38.58,32) 38.58,31.85 38.18,31.45 38.18,28.47 38.63,28.02 38.63,27.25 38.18,26.8 38.18,24.4 38.63,23.95 38.63,21.99 38.18,21.54 38.18,21.2 v2(38.58,20.8)
  BOTTOM w0.12: R342.1 v2(38.58,20.8)
DDR2_BA0: length 48.5
  TOP w0.12: v2(38.58,36.8) U26.M2 ; v2(38.58,25.6) U25.M2 ; U11.U23 v2(60.19,43.21)
  SIG_L5 w0.094: v2(38.58,25.6) 38.94,25.97 38.94,32.3 38.18,33.06 38.18,36.28 38.58,36.68 v2(38.58,36.8)
  SIG_L8 w0.094: v2(38.58,36.8) 38.18,37.2 38.18,39.07 40.26,41.15 48.39,41.15 48.77,41.53 48.77,42.16 49.26,42.65 49.26,42.77 49.05,42.97 49.05,43.09 49.14,43.17 49.25,43.17 49.45,42.97 49.57,42.97 49.65,43.05 49.65,43.17 49.45,43.37 49.45,43.48 49.54,43.57 49.65,43.57 49.85,43.37 49.97,43.37 50.05,43.45 50.05,43.57 49.85,43.77 49.85,43.88 49.93,43.97 50.05,43.97 50.25,43.76 50.37,43.76 50.45,43.85 50.45,43.96 50.25,44.16 50.25,44.28 50.33,44.36 50.45,44.36 50.65,44.16 50.77,44.16 50.85,44.25 50.85,44.36 50.65,44.56 50.65,44.68 50.73,44.76 50.85,44.76 51.05,44.56 51.17,44.56 51.25,44.64 51.25,44.76 51.05,44.96 51.05,45.08 51.13,45.16 51.25,45.16 51.45,44.96 51.57,44.96 51.84,45.23 59.22,45.23 59.23,45.23 59.5,45.23 60.19,44.54 v2(60.19,43.21)
  BOTTOM w0.12: v2(38.58,25.6) 38.98,26 38.98,26.6 R350.1
DDR2_BA1: length 49.5
  TOP w0.12: v2(37.78,31.2) U26.N8 ; v2(37.78,20) U25.N8 ; U11.U27 v2(56.99,43.21)
  SIG_L8 w0.094: v2(37.78,31.2) 37.38,30.8 37.38,29.92 37.85,29.46 37.85,27.34 37.38,26.87 37.38,24.33 37.85,23.87 37.85,21.75 37.38,21.29 37.38,20.4 v2(37.78,20)
  SIG_L10 w0.094: v2(37.78,31.2) 37.78,31.43 38.18,31.83 38.18,32.21 42.37,36.4 42.75,36.4 42.98,36.64 42.98,36.97 43.22,37.2 43.55,37.2 43.78,37.44 43.78,37.77 45.51,39.5 45.88,39.5 45.97,39.41 45.97,38.94 46.05,38.86 46.17,38.86 46.25,38.94 46.25,39.41 46.33,39.5 46.45,39.5 46.53,39.41 46.53,38.94 46.61,38.86 46.73,38.86 46.81,38.94 46.81,39.41 46.9,39.5 47.01,39.5 47.09,39.41 47.09,38.94 47.18,38.86 47.29,38.86 47.38,38.94 47.38,39.41 47.46,39.5 47.58,39.5 47.66,39.41 47.66,38.94 47.74,38.86 47.86,38.86 47.94,38.94 47.94,39.41 48.02,39.5 48.14,39.5 48.22,39.41 48.22,38.94 48.3,38.86 48.42,38.86 48.5,38.94 48.5,39.41 48.59,39.5 48.7,39.5 48.79,39.41 48.79,38.94 48.87,38.86 48.99,38.86 49.07,38.94 49.07,39.41 49.15,39.5 49.27,39.5 49.35,39.41 49.35,38.94 49.43,38.86 49.55,38.86 49.63,38.94 49.63,39.41 49.71,39.5 51.05,39.5 55.94,44.38 56.34,44.38 56.56,44.16 56.56,43.89 56.99,43.47 v2(56.99,43.21)
  BOTTOM w0.12: v2(37.78,20) 38.18,19.6 38.18,19 R353.1
DDR2_BA2: length 49.2
  TOP w0.12: v2(38.58,24.8) U25.M3 ; U11.U26 v2(57.79,43.21) ; v2(38.58,36) U26.M3
  INT_L3 w0.094: v2(38.58,24.8) 38.18,25.2 38.18,32.29 39.37,33.48 39.37,34.72 38.58,35.51 v2(38.58,36)
  SIG_L8 w0.094: v2(38.58,36) 38.98,36.4 38.98,38.73 39.21,38.96 39.21,39.08 39.01,39.28 39.01,39.39 39.1,39.48 39.21,39.48 39.41,39.28 39.53,39.28 39.61,39.36 39.61,39.48 39.41,39.68 39.41,39.79 39.49,39.88 39.61,39.88 39.81,39.68 39.93,39.68 40.01,39.76 40.01,39.87 39.81,40.08 39.81,40.19 39.89,40.27 40.01,40.27 40.21,40.07 40.33,40.07 40.41,40.16 40.41,40.27 40.21,40.47 40.21,40.59 40.29,40.67 40.41,40.67 40.61,40.47 40.73,40.47 41.15,40.89 48.77,40.89 49.37,41.5 49.37,41.61 49.11,41.88 49.11,41.99 49.19,42.08 49.31,42.08 49.57,41.81 49.69,41.81 49.77,41.9 49.77,42.01 49.51,42.28 49.51,42.39 49.59,42.48 49.7,42.48 49.97,42.21 50.09,42.21 50.17,42.29 50.17,42.41 49.9,42.68 49.9,42.79 49.99,42.87 50.1,42.87 50.37,42.61 50.48,42.61 50.57,42.69 50.57,42.81 50.3,43.07 50.3,43.19 50.39,43.27 50.5,43.27 50.77,43.01 50.88,43.01 50.97,43.09 50.97,43.21 50.7,43.47 50.7,43.59 50.78,43.67 50.9,43.67 51.16,43.41 51.28,43.41 51.36,43.49 51.36,43.61 51.1,43.87 51.1,43.99 51.18,44.07 51.3,44.07 51.56,43.81 51.68,43.81 51.76,43.89 51.76,44.01 51.5,44.27 51.5,44.39 51.58,44.47 51.7,44.47 51.96,44.21 52.08,44.21 52.3,44.43 57.93,44.43 58.17,44.2 58.17,43.56 57.81,43.21 v2(57.79,43.21)
  BOTTOM w0.12: R352.1 v2(38.58,24.8)
DDR2_CASN: length 49
  TOP w0.12: v2(40.18,36) U26.K3 ; U11.U28 v2(56.19,43.21) ; v2(40.18,24.8) U25.K3
  INT_L3 w0.094: v2(40.18,36) 40.18,35.71 40.89,35 40.89,32.65 40.58,32.33 40.58,30.23 41.02,29.79 41.02,28.14 39.78,26.9 39.78,25.2 v2(40.18,24.8)
  SIG_L8 w0.094: v2(56.19,43.21) 55.6,43.21 55.12,43.69 52.58,43.69 49.28,40.39 49.28,39.5 48.64,38.86 47.55,38.86 47.47,38.94 47.47,39.41 47.39,39.5 47.27,39.5 47.19,39.41 47.19,38.94 47.11,38.86 46.99,38.86 46.91,38.94 46.91,39.41 46.82,39.5 46.71,39.5 46.62,39.41 46.62,38.94 46.54,38.86 46.43,38.86 46.34,38.94 46.34,39.41 46.26,39.5 46.14,39.5 46.06,39.41 46.06,38.94 45.98,38.86 45.86,38.86 45.78,38.94 45.78,39.41 45.7,39.5 45.58,39.5 45.5,39.41 45.5,38.94 45.41,38.86 45.3,38.86 45.22,38.94 45.22,39.41 45.13,39.5 45.02,39.5 44.93,39.41 44.93,38.94 44.85,38.86 44.73,38.86 44.65,38.94 44.65,39.41 44.57,39.5 44.45,39.5 44.37,39.41 44.37,38.94 44.29,38.86 44.17,38.86 44.09,38.94 44.09,39.41 44,39.5 43.89,39.5 43.81,39.41 43.81,38.94 43.72,38.86 43.61,38.86 43.52,38.94 43.52,39.41 43.44,39.5 43.32,39.5 43.24,39.41 43.24,38.94 43.16,38.86 43.04,38.86 42.96,38.94 42.96,39.41 42.88,39.5 42.76,39.5 42.68,39.41 42.68,38.94 42.6,38.86 42.48,38.86 42.4,38.94 42.4,39.41 42.31,39.5 42.2,39.5 42.11,39.41 42.11,38.94 42.03,38.86 41.91,38.86 41.83,38.94 41.83,39.41 41.75,39.5 41.63,39.5 41.55,39.41 41.55,38.94 41.47,38.86 41.35,38.86 41.27,38.94 41.27,39.41 41.19,39.5 40.89,39.5 40.58,39.19 40.58,36.4 v2(40.18,36)
  BOTTOM w0.12: R349.1 v2(40.18,24.8)
DDR2_CKE: length 54.3
  TOP w0.12: v2(40.18,19.2) U25.K9 ; U11.U24 v2(59.39,43.21) ; v2(40.18,30.4) U26.K9
  SIG_L10 w0.094: v2(40.18,19.2) 39.78,19.6 39.78,21.54 40.13,21.89 40.13,23.98 39.78,24.33 39.78,26.75 40.26,27.22 40.26,28.05 39.78,28.52 39.78,30 v2(40.18,30.4) 40.18,30.43 39.78,30.83 39.78,32.92 42.29,35.43 48.77,35.43 50.25,36.91 50.25,37.03 50.05,37.23 50.05,37.35 50.13,37.43 50.24,37.43 50.45,37.23 50.56,37.23 50.64,37.31 50.64,37.43 50.44,37.63 50.44,37.74 50.53,37.83 50.64,37.83 50.84,37.63 50.96,37.63 51.04,37.71 51.04,37.83 50.84,38.03 50.84,38.14 50.93,38.23 51.04,38.23 51.24,38.02 51.36,38.02 51.44,38.11 51.44,38.22 51.24,38.42 51.24,38.54 51.32,38.62 51.44,38.62 51.64,38.42 51.76,38.42 51.84,38.51 51.84,38.62 51.64,38.82 51.64,38.94 51.72,39.02 51.84,39.02 52.04,38.82 52.16,38.82 52.24,38.9 52.24,39.02 52.04,39.22 52.04,39.34 52.12,39.42 52.24,39.42 52.44,39.22 52.56,39.22 52.64,39.3 52.64,39.42 52.44,39.62 52.44,39.74 52.52,39.82 52.64,39.82 52.84,39.62 52.95,39.62 53.04,39.7 53.04,39.82 52.84,40.02 52.84,40.14 52.92,40.22 53.04,40.22 53.24,40.02 53.35,40.02 53.98,40.64 53.98,41.66 55.95,43.63 56.32,43.63 56.61,43.34 56.61,43.05 56.83,42.83 59.01,42.83 v2(59.39,43.21)
  BOTTOM w0.12: R348.1 v2(40.18,19.2) ; v2(59.39,43.21) 59.39,43.23 59.01,43.61 57.62,43.61 57.39,43.37 57.39,42.24 57.15,42.01 55.94,42.01 R334.1
DDR2_CLK0: length 48.9
  TOP w0.12: v2(40.98,32) U26.J7 ; U11.T28 v2(56.19,42.41) ; v2(40.98,20.8) U25.J7
  SIG_L10 w0.094: v2(56.19,42.41) 56.12,42.41 55.26,41.55 55.26,41.31 55.35,41.23 55.59,41.23 55.68,41.15 55.68,41.03 55.59,40.95 55.35,40.95 55.26,40.87 55.26,40.75 55.35,40.67 55.59,40.67 55.68,40.58 55.68,40.47 55.59,40.39 55.35,40.39 55.26,40.3 55.26,36.79 50.84,32.37 49.49,32.37 49.12,32.74 49.12,33.8 49.02,33.89 48.83,33.89 48.74,33.8 48.74,33.08 48.41,32.75 47.89,32.75 47.57,33.08 47.57,33.8 47.47,33.89 47.29,33.89 47.19,33.8 47.19,33.08 46.86,32.75 46.35,32.75 46.02,33.08 46.02,33.8 45.92,33.89 45.74,33.89 45.64,33.8 45.64,33.08 45.31,32.75 44.8,32.75 44.47,33.08 44.47,33.8 44.37,33.89 44.19,33.89 44.09,33.8 44.09,33.08 43.76,32.75 43.25,32.75 42.92,33.08 42.92,33.8 42.82,33.89 42.64,33.89 42.54,33.8 42.54,33.08 42.22,32.75 40.91,32.75 40.58,32.42 40.58,32.1 40.67,32 v2(40.98,32) 40.98,32 41.31,32 41.8,31.52 41.8,22.39 40.58,21.17 40.58,20.9 40.68,20.8 v2(40.98,20.8)
  BOTTOM w0.12: R281.1 v2(40.98,20.8)
DDR2_CLK0N: length 48.8
  TOP w0.12: v2(40.18,32) U26.K7 ; U11.T27 v2(56.99,42.41) ; v2(40.18,20.8) U25.K7
  SIG_L10 w0.094: v2(40.18,20.8) 40.18,21.34 41.4,22.56 41.4,31.35 41.15,31.6 40.58,31.6 v2(40.18,32) 40.18,32.02 40.19,32.03 40.19,32.59 40.75,33.15 42.05,33.15 42.14,33.24 42.14,33.96 42.47,34.29 42.99,34.29 43.32,33.96 43.32,33.24 43.41,33.15 43.6,33.15 43.69,33.24 43.69,33.96 44.02,34.29 44.54,34.29 44.87,33.96 44.87,33.24 44.96,33.15 45.15,33.15 45.24,33.24 45.24,33.96 45.57,34.29 46.09,34.29 46.42,33.96 46.42,33.24 46.51,33.15 46.7,33.15 46.79,33.24 46.79,33.96 47.12,34.29 47.64,34.29 47.97,33.96 47.97,33.24 48.06,33.15 48.25,33.15 48.34,33.24 48.34,33.96 48.67,34.29 49.19,34.29 49.52,33.96 49.52,32.91 49.66,32.77 50.67,32.77 54.86,36.96 54.86,41.66 56.01,42.8 56.35,42.8 56.75,42.41 v2(56.99,42.41)
  BOTTOM w0.12: R280.1 v2(40.18,20.8)
DDR2_CLK_TRM: length 1.6
  BOTTOM w0.12: R280.2 R281.2 C334.2
DDR2_CSN0: length 49.7
  TOP w0.12: U11.P24 v2(59.39,40.01) ; v2(39.38,25.6) U25.L2 ; v2(39.38,36.8) U26.L2
  SIG_L5 w0.094: v2(59.39,40.01) 58.88,40.51 54.61,40.51 54.48,40.39 54.48,39.46 54.39,39.37 54.2,39.37 54.11,39.46 54.11,40.18 54.02,40.26 53.91,40.26 53.82,40.18 53.82,39.45 53.74,39.37 53.63,39.37 53.54,39.45 53.54,40.18 53.46,40.26 53.34,40.26 53.26,40.18 53.26,39.45 53.18,39.37 53.06,39.37 52.98,39.45 52.98,40.18 52.9,40.26 52.78,40.26 52.7,40.18 52.7,39.45 52.61,39.37 52.5,39.37 52.41,39.45 52.41,40.18 52.33,40.26 52.22,40.26 52.13,40.18 52.13,39.45 52.05,39.37 51.93,39.37 51.85,39.45 51.85,40.18 51.77,40.26 51.65,40.26 51.57,40.18 51.57,39.45 51.49,39.37 51.37,39.37 51.29,39.45 51.29,40.18 51.2,40.26 51.09,40.26 51.01,40.18 51.01,39.45 50.92,39.37 50.81,39.37 50.72,39.45 50.72,40.18 50.64,40.26 50.52,40.26 50.44,40.18 50.44,39.45 49.85,38.86 40.64,38.86 39.78,38 39.78,37.24 39.38,36.84 v2(39.38,36.8) 38.98,36.4 38.98,33.03 39.74,32.26 39.74,29.91 39.62,29.79 39.62,29.63 39.74,29.51 39.74,29.35 39.62,29.23 39.62,29.07 39.74,28.95 39.74,28.79 39.62,28.66 39.62,28.5 39.74,28.38 39.74,28.22 39.62,28.1 39.62,27.94 39.74,27.82 39.74,27.66 39.62,27.54 39.62,27.38 39.74,27.26 39.74,27.09 39.62,26.97 39.62,26.81 39.74,26.69 39.74,25.97 v2(39.38,25.6)
  BOTTOM w0.12: v2(39.38,25.6) 39.78,26 39.78,26.6 R351.1
DDR2_D0: length 20.5
  TOP w0.12: v2(45.78,20.8) U25.D7 ; U11.E26 v2(57.79,32.81)
  INT_L3 w0.094: v2(45.78,20.8) 46.23,21.25 46.23,23.37 47.24,24.38 48.51,24.38 53.98,29.84 53.98,31.79 54.99,32.81 v2(57.79,32.81)
DDR2_D1: length 20.5
  TOP w0.12: v2(46.58,25.6) U25.C2 ; U11.G25 v2(58.59,34.41)
  INT_L3 w0.094: v2(46.58,25.6) 47,26.02 48.63,26.02 51.18,28.57 51.18,29.24 51.26,29.32 51.35,29.32 51.44,29.41 51.44,29.52 51.35,29.61 51.26,29.61 51.18,29.69 51.18,29.81 51.26,29.89 51.35,29.89 51.44,29.97 51.44,30.09 51.35,30.17 51.26,30.17 51.18,30.25 51.18,30.37 51.26,30.45 51.35,30.45 51.44,30.53 51.44,30.65 51.35,30.73 51.26,30.73 51.18,30.82 51.18,30.93 51.26,31.02 51.35,31.02 51.44,31.1 51.44,31.22 51.35,31.3 51.26,31.3 51.18,31.38 51.18,31.5 51.26,31.58 51.35,31.58 51.44,31.66 51.44,31.78 51.35,31.86 51.26,31.86 51.18,31.94 51.18,32.26 52.95,34.03 58.21,34.03 v2(58.59,34.41)
DDR2_D2: length 20.4
  TOP w0.12: v2(48.18,24.8) U25.A3 ; U11.F25 v2(58.59,33.61)
  INT_L3 w0.094: v2(58.59,33.61) 58.37,33.61 57.99,33.23 53.18,33.23 53.09,33.13 53.09,32.53 53.17,32.45 53.51,32.45 53.59,32.36 53.59,32.25 53.51,32.16 53.17,32.16 53.09,32.08 53.09,31.4 53.17,31.32 53.51,31.32 53.59,31.24 53.59,31.12 53.51,31.04 53.17,31.04 53.09,30.95 53.09,30.84 53.17,30.75 53.51,30.75 53.59,30.67 53.59,30.55 53.51,30.47 53.17,30.47 53.09,30.39 53.09,30.27 53.17,30.19 53.51,30.19 53.59,30.11 53.59,29.97 48.43,24.8 v2(48.18,24.8)
DDR2_D3: length 20.5
  TOP w0.12: U11.F24 v2(59.39,33.61) ; v2(47.38,20) U25.B8
  INT_L3 w0.094: v2(47.38,20) 51.18,23.8 51.18,25.65 56.58,31.05 56.58,31.31 56.9,31.62 57.94,31.62 58.21,31.89 58.21,32.17 58.42,32.38 58.78,32.38 59.01,32.62 59.01,32.96 59.39,33.34 v2(59.39,33.61)
DDR2_D4: length 20.3
  TOP w0.12: v2(48.18,25.6) U25.A2 ; U11.F26 v2(57.79,33.61)
  INT_L3 w0.094: v2(48.18,25.6) 48.72,25.6 51.82,28.7 51.82,29.46 51.9,29.54 52.24,29.54 52.32,29.63 52.32,29.74 52.24,29.83 51.9,29.83 51.82,29.91 51.82,30.03 51.9,30.11 52.24,30.11 52.32,30.19 52.32,30.31 52.24,30.39 51.9,30.39 51.82,30.47 51.82,30.59 51.9,30.67 52.24,30.67 52.32,30.75 52.32,30.87 52.24,30.95 51.9,30.95 51.82,31.04 51.82,31.15 51.9,31.24 52.24,31.24 52.32,31.32 52.32,31.43 52.24,31.52 51.9,31.52 51.82,31.6 51.82,31.72 51.9,31.8 52.24,31.8 52.32,31.88 52.32,32 52.24,32.08 51.9,32.08 51.82,32.16 51.82,32.38 53.04,33.61 v2(57.79,33.61)
DDR2_D5: length 20.4
  TOP w0.12: v1(50.29,28.19) 50.29,27.04 50.41,26.92 51.95,26.92 52.07,27.04 52.07,31.62 54.05,33.61 56.99,33.61 U11.F27 ; v2(46.58,24.8) U25.C3
  SIG_L10 w0.094: v1(50.29,28.19) 48.51,28.19 46.99,26.67 46.99,25.21 v2(46.58,24.8)
DDR2_D6: length 20.1
  TOP w0.12: U11.E27 56.99,32.81 56.17,32.81 55.68,32.32 55.68,31.17 55.58,31.06 55.1,31.06 54.99,30.96 54.99,30.81 55.1,30.7 55.58,30.7 55.68,30.6 55.68,30.45 55.58,30.34 55.1,30.34 54.99,30.24 54.99,30.09 55.1,29.98 55.58,29.98 55.68,29.88 55.68,29.73 55.58,29.62 55.1,29.62 54.99,29.52 54.99,29.37 55.1,29.26 55.58,29.26 55.68,29.16 55.68,28.63 48.26,21.21 47.79,21.21 U25.A7
DDR2_D7: length 20.1
  TOP w0.12: U25.C8 46.55,20.77 47.06,20.77 47.37,21.07 47.37,21.46 47.5,21.59 48.13,21.59 53.98,27.43 53.98,29.06 54.08,29.16 54.25,29.16 54.36,29.27 54.36,29.42 54.25,29.52 54.08,29.52 53.98,29.63 53.98,29.77 54.08,29.88 54.25,29.88 54.36,29.99 54.36,30.13 54.25,30.24 54.08,30.24 53.98,30.35 53.98,30.49 54.08,30.6 54.25,30.6 54.36,30.7 54.36,30.85 54.25,30.96 54.08,30.96 53.98,31.06 53.98,31.88 55.3,33.21 U11.E28
DDR2_D8: length 28.4
  TOP w0.12: v2(47.37,23.88) 45.11,23.88 U25.E3 ; U11.H23 v2(60.19,35.21)
  INT_L3 w0.094: v2(60.19,35.21) 59.78,34.8 59.18,34.8 58.96,34.58 58.96,33.4 58.79,33.23 58.48,33.23 58.17,32.92 58.17,32.59 57.96,32.38 55.37,32.38 54.86,31.88 54.86,30.1 50.8,26.04 50.8,24 48.26,21.46 46.86,21.46 46.74,21.59 46.74,23.24 v2(47.37,23.88)
DDR2_D9: length 28.8
  TOP w0.12: v2(42.58,24.8) U25.H3 ; U11.H25 v2(58.59,35.21)
  BOTTOM w0.12: v2(58.59,35.21) 58.45,35.21 58.05,34.81 57.41,34.81 57.02,34.42 53.47,34.42 51.31,32.26 51.31,31.07 51.2,30.96 51.16,30.96 51.05,30.86 51.05,30.71 51.16,30.6 51.2,30.6 51.31,30.5 51.31,30.35 51.2,30.24 51.16,30.24 51.05,30.14 51.05,29.99 51.16,29.88 51.2,29.88 51.31,29.78 51.31,29.63 51.2,29.52 51.16,29.52 51.05,29.42 51.05,29.27 51.16,29.16 51.2,29.16 51.31,29.06 51.31,28.91 51.2,28.8 51.16,28.8 51.05,28.7 51.05,28.55 51.16,28.44 51.2,28.44 51.31,28.34 51.31,28.19 51.2,28.08 51.16,28.08 51.05,27.98 51.05,27.83 51.16,27.72 51.2,27.72 51.31,27.62 51.31,27.47 51.2,27.36 51.16,27.36 51.05,27.26 51.05,27.11 51.16,27 51.2,27 51.31,26.9 51.31,26.75 51.2,26.64 51.16,26.64 51.05,26.54 51.05,26.39 51.16,26.28 51.2,26.28 51.31,26.18 51.31,25.91 48.01,22.61 44.78,22.61 v2(42.58,24.8)
DDR2_D10: length 28.5
  TOP w0.12: v2(45.72,21.84) 42.93,21.84 42.58,21.5 42.58,20.8 U25.H8 ; U11.H24 v2(59.39,35.21)
  BOTTOM w0.12: v2(59.39,35.21) 59.39,35 58.99,34.6 58.99,34.24 58.75,34.01 58.42,34.01 58.19,33.77 58.19,33.44 57.95,33.21 53.53,33.21 52.07,31.75 52.07,25.53 48.39,21.84 v2(45.72,21.84)
DDR2_D11: length 28.7
  TOP w0.12: U11.H26 v2(57.79,35.21) ; v2(43.38,25.6) U25.G2
  BOTTOM w0.12: v2(57.79,35.21) 57.63,35.05 57.15,35.05 56.9,34.8 53.21,34.8 49.78,31.37 49.78,30.69 49.89,30.59 50.06,30.59 50.16,30.48 50.16,30.33 50.06,30.23 49.89,30.23 49.78,30.12 49.78,29.98 49.89,29.87 50.06,29.87 50.16,29.76 50.16,29.62 50.06,29.51 49.89,29.51 49.78,29.4 49.78,27.34 49.89,27.24 50.06,27.24 50.16,27.13 50.16,26.98 50.06,26.88 49.89,26.88 49.78,26.77 49.78,26.62 49.89,26.52 50.06,26.52 50.16,26.41 50.16,26.26 50.06,26.16 49.89,26.16 49.78,26.05 49.78,25.9 49.89,25.8 50.06,25.8 50.16,25.69 50.16,25.54 50.06,25.44 49.89,25.44 49.78,25.33 49.78,24.9 47.87,22.99 44.96,22.99 43.38,24.56 v2(43.38,25.6)
DDR2_D12: length 28.2
  TOP w0.12: U11.G26 v2(57.79,34.41) ; v2(41.78,20.8) U25.H7
  INT_L3 w0.094: v2(41.78,20.8) 42.36,21.38 42.36,21.5 42.02,21.84 42.02,21.96 42.11,22.04 42.22,22.04 42.56,21.7 42.68,21.7 42.76,21.78 42.76,21.9 42.42,22.24 42.42,22.36 42.5,22.44 42.62,22.44 42.96,22.1 43.08,22.1 43.16,22.18 43.16,22.3 42.82,22.64 42.82,22.75 42.9,22.84 43.02,22.84 43.36,22.5 43.48,22.5 43.78,22.8 43.78,26.51 45.97,28.7 47.12,28.7 52.82,34.41 v2(57.79,34.41)
DDR2_D13: length 28.4
  TOP w0.12: U11.J25 v2(58.59,36.01) ; v2(44.18,25.6) U25.F2
  BOTTOM w0.12: v2(58.59,36.01) 58.19,35.61 57.62,35.61 57.32,35.31 56.93,35.31 56.8,35.18 52.96,35.18 49.4,31.62 49.4,31.17 49.3,31.07 49.25,31.07 49.15,30.96 49.15,30.81 49.25,30.71 49.3,30.71 49.4,30.6 49.4,30.45 49.3,30.35 49.25,30.35 49.15,30.24 49.15,30.09 49.25,29.99 49.3,29.99 49.4,29.88 49.4,29.73 49.3,29.63 49.25,29.63 49.15,29.52 49.15,29.37 49.25,29.27 49.3,29.27 49.4,29.16 49.4,29.01 49.3,28.91 49.25,28.91 49.15,28.8 49.15,28.65 49.25,28.55 49.3,28.55 49.4,28.44 49.4,28.29 49.3,28.19 49.25,28.19 49.15,28.08 49.15,27.93 49.25,27.83 49.3,27.83 49.4,27.72 49.4,27.57 49.3,27.47 49.25,27.47 49.15,27.36 49.15,27.21 49.25,27.11 49.3,27.11 49.4,27 49.4,26.86 49.3,26.75 49.25,26.75 49.15,26.64 49.15,26.5 49.25,26.39 49.3,26.39 49.4,26.28 49.4,26.14 49.3,26.03 49.25,26.03 49.15,25.93 49.15,25.78 49.25,25.67 49.3,25.67 49.4,25.57 49.4,25.13 47.64,23.37 45.09,23.37 44.18,24.27 v2(44.18,25.6)
DDR2_D14: length 28.6
  TOP w0.12: v2(44.18,20) U25.F8 ; U11.J26 v2(57.79,36.01)
  SIG_L10 w0.094: v2(57.79,36.01) 57.21,35.43 55.88,35.43 51.82,31.37 51.82,27.43 49.34,24.96 49.34,24.84 49.48,24.7 49.48,24.59 49.4,24.5 49.28,24.5 49.14,24.64 49.02,24.64 48.94,24.56 48.94,24.44 49.08,24.3 49.08,24.19 49,24.1 48.88,24.1 48.74,24.24 48.63,24.24 48.54,24.16 48.54,24.04 48.68,23.9 48.68,23.79 48.6,23.71 48.48,23.71 48.34,23.84 48.23,23.84 48.14,23.76 48.14,23.64 48.28,23.51 48.28,23.39 48.2,23.31 48.08,23.31 47.94,23.44 47.83,23.44 47.75,23.36 47.75,23.24 47.88,23.11 47.88,22.99 47.8,22.91 47.68,22.91 47.55,23.05 47.43,23.05 47.35,22.96 47.35,22.85 47.48,22.71 47.48,22.59 47.4,22.51 47.28,22.51 47.15,22.65 47.03,22.65 46.95,22.56 46.95,22.45 47.09,22.31 47.09,22.19 47,22.11 46.89,22.11 46.75,22.25 46.63,22.25 46.55,22.17 46.55,22.05 46.69,21.91 46.69,21.79 46.6,21.71 46.49,21.71 46.35,21.85 46.23,21.85 46.15,21.77 46.15,21.65 46.29,21.51 46.29,21.4 46.21,21.31 46.09,21.31 45.95,21.45 45.83,21.45 45.34,20.95 45.34,20.66 45.13,20.45 44.63,20.45 v2(44.18,20)
DDR2_D15: length 28.8
  TOP w0.12: U11.J24 v2(59.39,36.01) ; v2(44.18,20.8) U25.F7
  BOTTOM w0.12: v2(59.39,36.01) 59.37,36.01 58.99,35.62 58.99,34.98 58.81,34.81 58.42,34.81 58.19,34.57 58.19,34.24 57.95,34.01 57.39,34.01 57.28,33.9 57.28,33.76 57.18,33.66 57.03,33.66 56.92,33.76 56.92,33.9 56.82,34.01 56.67,34.01 56.56,33.9 56.56,33.76 56.46,33.66 56.31,33.66 56.2,33.76 56.2,33.9 56.1,34.01 55.95,34.01 55.85,33.9 55.85,33.76 55.74,33.66 55.59,33.66 55.49,33.76 55.49,33.9 55.38,34.01 55.23,34.01 55.13,33.9 55.13,33.76 55.02,33.66 54.87,33.66 54.77,33.76 54.77,33.9 54.66,34.01 53.69,34.01 51.69,32 51.69,25.78 48.15,22.24 45.36,22.24 44.18,21.07 v2(44.18,20.8)
DDR2_D16: length 20.8
  TOP w0.12: v1(50.99,37.15) 50.67,36.83 50.67,35.31 49.02,33.66 45.97,33.66 45.38,33.06 U26.D7 ; U11.L22 v2(60.99,37.61)
  INT_L3 w0.094: v2(60.99,37.61) 60.56,38.03 59.95,38.03 59.81,38.17 59.81,38.49 59.47,38.83 52.67,38.83 v1(50.99,37.15)
DDR2_D17: length 21.1
  TOP w0.12: U11.K20 v2(62.59,36.81) ; v2(46.58,31.2) U26.C8
  INT_L3 w0.094: v2(46.58,31.2) 45.97,31.81 45.97,32.51 46.23,32.77 50.04,32.77 53.7,36.43 62.21,36.43 v2(62.59,36.81)
DDR2_D18: length 20.5
  TOP w0.12: U26.A2 v2(48.18,36.8) 48.23,36.8 48.64,37.21 48.64,40.01 v1(48.89,40.26) ; U11.K21 v2(61.79,36.81)
  INT_L3 w0.094: v2(61.79,36.81) 61.36,37.23 61.36,38.59 61.12,38.83 60.83,38.83 60.61,39.05 60.61,39.34 60.32,39.63 60.03,39.63 59.81,39.85 59.81,40.14 59.56,40.39 54.74,40.39 54.61,40.26 v1(48.89,40.26)
DDR2_D19: length 21
  TOP w0.12: U11.L23 v2(60.19,37.61) ; v2(46.58,36.8) U26.C2
  INT_L3 w0.094: v2(60.19,37.61) 59.92,37.61 59.54,37.98 59.53,37.98 59.49,38.03 57.33,38.03 57.25,37.95 57.25,37.67 57.16,37.59 57.05,37.59 56.96,37.67 56.96,37.95 56.88,38.03 56.77,38.03 56.68,37.95 56.68,37.67 56.6,37.59 56.48,37.59 56.4,37.67 56.4,37.95 56.32,38.03 56.2,38.03 56.12,37.95 56.12,37.67 56.04,37.59 55.92,37.59 55.84,37.67 55.84,37.95 55.75,38.03 55.64,38.03 55.55,37.95 55.55,37.67 55.47,37.59 55.36,37.59 55.27,37.67 55.27,37.95 55.19,38.03 55.07,38.03 54.99,37.95 54.99,37.67 54.91,37.59 54.79,37.59 54.71,37.67 54.71,37.95 54.63,38.03 53.78,38.03 51.05,35.31 49.31,35.31 49.21,35.4 49.21,36.39 48.35,37.25 47.03,37.25 v2(46.58,36.8)
DDR2_D20: length 20.7
  TOP w0.12: U11.L24 v2(59.39,37.61) ; v2(45.78,36) U26.C3
  INT_L3 w0.094: v2(59.39,37.61) 59.12,37.61 58.64,37.12 53.38,37.12 49.78,33.53 47.75,33.53 47.62,33.66 47.62,34.67 48.64,35.69 48.64,36.2 48.39,36.45 46.99,36.45 46.55,36 v2(45.78,36)
DDR2_D21: length 20.9
  TOP w0.12: U11.J23 v2(60.19,36.01) ; v2(47.38,31.2) U26.B8
  INT_L3 w0.094: v2(60.19,36.01) 59.81,35.63 57.6,35.63 56.77,34.8 56.55,34.8 56.47,34.88 56.47,35.22 56.38,35.31 56.27,35.31 56.18,35.22 56.18,34.88 56.1,34.8 55.98,34.8 55.9,34.88 55.9,35.22 55.82,35.31 55.7,35.31 55.62,35.22 55.62,34.88 55.54,34.8 55.42,34.8 55.34,34.88 55.34,35.22 55.26,35.31 55.14,35.31 55.06,35.22 55.06,34.88 54.97,34.8 54.86,34.8 54.77,34.88 54.77,35.22 54.69,35.31 54.57,35.31 54.49,35.22 54.49,34.88 54.41,34.8 54.29,34.8 54.21,34.88 54.21,35.22 54.13,35.31 54.01,35.31 53.93,35.22 53.93,34.88 53.85,34.8 53.73,34.8 53.65,34.88 53.65,35.22 53.56,35.31 53.45,35.31 53.36,35.22 53.36,34.88 53.28,34.8 52.7,34.8 49.53,31.62 47.8,31.62 v2(47.38,31.2)
DDR2_D22: length 20.7
  TOP w0.12: v2(48.18,36) U26.A3 ; U11.K22 v2(60.99,36.81)
  INT_L3 w0.094: v2(48.18,36) 46.61,34.43 46.61,33.4 46.86,33.15 49.91,33.15 53.54,36.78 58.78,36.78 59.22,37.21 60.58,37.21 60.98,36.81 v2(60.99,36.81)
DDR2_D23: length 20.9
  TOP w0.12: U11.J20 v2(62.59,36.01) ; v2(48.18,32) U26.A7
  SIG_L5 w0.094: v2(48.18,32) 48.18,32.44 48.35,32.6 48.9,32.6 49.01,32.49 49.12,32.49 49.21,32.57 49.21,32.69 49.1,32.8 49.1,32.92 49.18,33 49.29,33 49.41,32.89 49.52,32.89 49.61,32.97 49.61,33.09 49.49,33.2 49.49,33.31 49.58,33.4 49.69,33.4 49.81,33.28 49.92,33.28 50,33.37 50,33.48 49.89,33.6 49.89,33.71 49.98,33.8 50.09,33.8 50.2,33.68 50.32,33.68 50.4,33.77 50.4,33.88 50.29,33.99 50.29,34.11 50.37,34.19 50.49,34.19 50.6,34.08 50.72,34.08 50.8,34.16 50.8,34.28 50.69,34.39 50.69,34.51 50.77,34.59 50.89,34.59 51,34.48 51.12,34.48 51.2,34.56 51.2,34.68 51.09,34.79 51.09,34.91 51.17,34.99 51.29,34.99 51.4,34.88 51.52,34.88 51.6,34.96 51.6,35.08 51.49,35.19 51.49,35.31 52.55,36.37 62.22,36.37 v2(62.59,36.01)
DDR2_D24: length 23.8
  TOP w0.12: v2(44.18,32) 44.15,32.04 44.15,32.69 43.52,33.32 43.52,33.92 43.64,34.04 48.77,34.04 50.29,35.56 50.29,37.72 50.42,37.85 55.37,37.85 55.61,37.61 56.99,37.61 U11.L27 ; v2(44.18,36) U26.E3
  INT_L3 w0.094: v2(44.18,32) v2(44.18,36)
DDR2_D25: length 24.4
  TOP w0.12: U11.L26 v2(57.79,37.61) ; v2(42.58,31.2) U26.H8
  BOTTOM w0.12: v2(57.79,37.61) 53.73,37.61 49.78,33.66 41.66,33.66 41.53,33.53 41.53,32.91 41.63,32.8 42.06,32.8 42.16,32.69 42.16,32.55 42.06,32.44 41.63,32.44 41.53,32.34 41.53,32.19 41.63,32.08 42.06,32.08 42.16,31.98 42.16,31.83 42.06,31.72 41.63,31.72 41.53,31.62 41.53,31.37 41.69,31.2 v2(42.58,31.2)
DDR2_D26: length 24
  TOP w0.12: U11.L25 v2(58.59,37.61) ; v2(42.58,32) U26.H7
  BOTTOM w0.12: v2(42.58,32) 42.58,32.77 42.7,32.89 43.67,32.89 43.77,33 43.77,33.17 43.88,33.27 44.03,33.27 44.13,33.17 44.13,33 44.24,32.89 44.39,32.89 44.49,33 44.49,33.17 44.6,33.27 44.75,33.27 44.85,33.17 44.85,33 44.96,32.89 45.11,32.89 45.21,33 45.21,33.17 45.32,33.27 45.47,33.27 45.57,33.17 45.57,33 45.68,32.89 45.83,32.89 45.93,33 45.93,33.17 46.04,33.27 46.19,33.27 46.29,33.17 46.29,33 46.4,32.89 46.55,32.89 46.65,33 46.65,33.17 46.76,33.27 46.91,33.27 47.01,33.17 47.01,33 47.12,32.89 47.27,32.89 47.37,33 47.37,33.17 47.48,33.27 47.63,33.27 47.73,33.17 47.73,33 47.84,32.89 47.99,32.89 48.09,33 48.09,33.17 48.2,33.27 48.34,33.27 48.45,33.17 48.45,33 48.56,32.89 48.7,32.89 48.81,33 48.81,33.17 48.92,33.27 49.06,33.27 49.17,33.17 49.17,33 49.27,32.89 49.53,32.89 53.84,37.21 58.16,37.21 58.56,37.61 v2(58.59,37.61)
